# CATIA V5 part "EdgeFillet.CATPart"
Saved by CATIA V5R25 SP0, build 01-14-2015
Part number: Part1
Bounding box of the stored display mesh (mm): x -55 to 55, y -155 to 25.782, z -44.572 to 40
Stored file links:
  E:\cadcim\GSD_cat_v5-6r2014\Part_files\EdgeFillet.CATPart
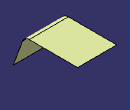
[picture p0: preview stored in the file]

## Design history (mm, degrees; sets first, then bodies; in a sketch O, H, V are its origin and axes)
Body1 (main body)
  Sketch1 on yz-plane, origin (0, 0, 0), H (0, 1, 0), V (0, 0, 1)
    point P1 (25.7818, 40)
    line L1 (25.7818, 40) -> (-124.2182, 40)
    line L2 (-124.2182, 40) -> (-155, -44.5723)
    point P3 (-155, -44.5723)
    length L1 = 150
    length L2 = 90
    angle L2 L1 = 110
    distance P1 H = 40
    distance P3 V = 155
    horizontal: L1 H
  Extrude1: Lim1 55, Lim2 55, Element1 Sketch1
  Fillet1: radius 20, on edge [face of Extrude1 from Sketch1.L1 | face of Extrude1 from Sketch1.L2]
